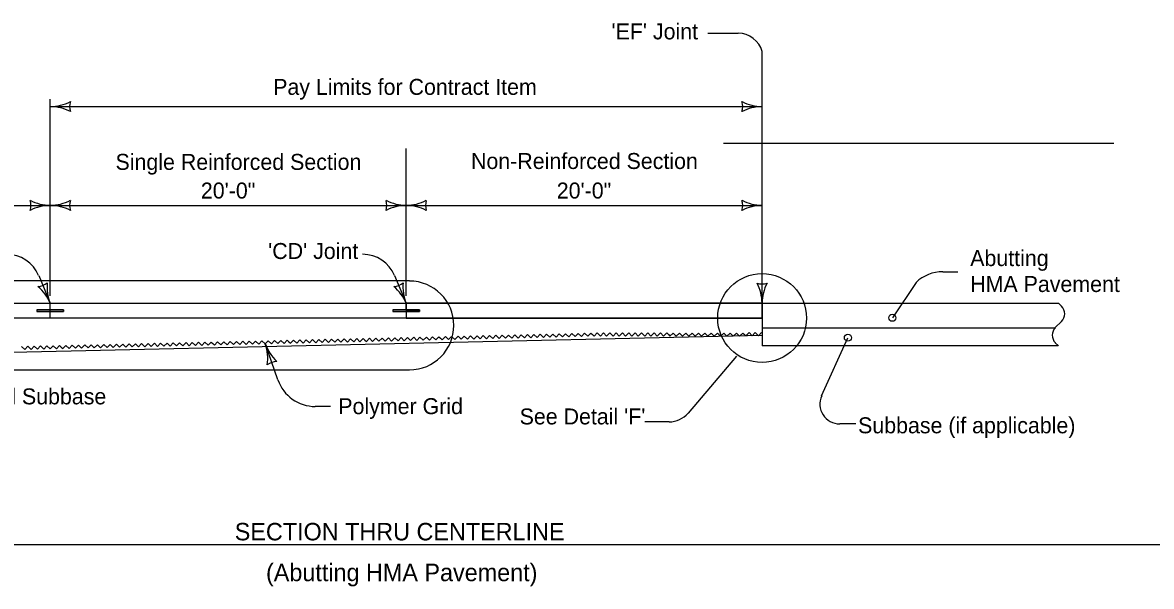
# Model space of a CAD drawing. Extents: x -2134860 to -2124557, y -2139046 to -2137324.
# Drawn here: x -2130560 to -2129429, y -2138083 to -2137518 of the extents above; entities that cross this region are included whole.
import ezdxf

# ---------------------------------------------------------------- set-up
doc = ezdxf.new("R2010")
doc.units = 0
for name, color, linetype in [('BridgeSuperStructureExisting', 7, 'Continuous'), ('dsnAlignmentCurveData', 7, 'Continuous'), ('dsnStdLabel', 7, 'Continuous'), ('TC_Barrier', 7, 'Continuous')]:
    doc.layers.add(name, color=color, linetype=linetype)

msp = doc.modelspace()

# ---------------------------------------------------------------- linework, layer by layer
at = {"layer": 'BridgeSuperStructureExisting'}
for p, q in [((-2129873.6, -2137528.5), (-2129843.1, -2137528.5)), ((-2129819.2, -2137799.1), (-2129819.2, -2137546.8)), ((-2130532, -2137791.7), (-2130532, -2137594.7)), ((-2130532, -2137602.1), (-2129819.2, -2137602.1)), ((-2129857.8, -2137638.6), (-2129466.9, -2137638.6)), ((-2130175.6, -2137791.7), (-2130175.6, -2137644.1)), ((-2130980.5, -2137701.1), (-2130532, -2137701.1)), ((-2130532, -2137701.1), (-2130175.6, -2137701.1)), ((-2130175.6, -2137701.1), (-2129819.2, -2137701.1)), ((-2130543.6, -2137771.4), (-2130532, -2137799.1)), ((-2130187.2, -2137771.3), (-2130175.6, -2137799.1)), ((-2129638.1, -2137767.6), (-2129623.3, -2137767.6)), ((-2130172.4, -2137776.8), (-2130977.5, -2137776.8)), ((-2129665.1, -2137778.2), (-2129688.8, -2137813.7)), ((-2130977.5, -2137799.1), (-2129819.2, -2137799.1)), ((-2130545.4, -2137805.6), (-2130518.7, -2137805.6)), ((-2130545.4, -2137807.5), (-2130518.7, -2137807.5)), ((-2130545.4, -2137807.5), (-2130518.7, -2137807.5)), ((-2130532, -2137814), (-2130532, -2137799.1)), ((-2130518.7, -2137805.6), (-2130518.7, -2137807.5)), ((-2130189, -2137805.6), (-2130162.3, -2137805.6)), ((-2130189, -2137807.5), (-2130162.3, -2137807.5)), ((-2129819.2, -2137799.1), (-2130175.6, -2137799.1)), ((-2130175.6, -2137799.1), (-2130175.6, -2137805.6)), ((-2130175.6, -2137799.1), (-2130175.6, -2137814)), ((-2130175.6, -2137805.6), (-2130162.3, -2137805.6)), ((-2130162.3, -2137807.5), (-2130175.6, -2137807.5)), ((-2130175.6, -2137807.5), (-2130175.6, -2137814)), ((-2130162.3, -2137805.6), (-2130162.3, -2137807.5)), ((-2130162.3, -2137805.6), (-2130162.3, -2137807.5)), ((-2129819.2, -2137814), (-2129819.2, -2137799.1)), ((-2129819.2, -2137799.1), (-2129522.4, -2137799.1)), ((-2129819.2, -2137799.1), (-2129819.2, -2137814)), ((-2129537, -2137799.1), (-2129537, -2137799.1)), ((-2129519.3, -2137802.2), (-2129522.4, -2137799.1)), ((-2129819.2, -2137814), (-2130977.5, -2137814)), ((-2130175.6, -2137814), (-2129819.2, -2137814)), ((-2129819.2, -2137814), (-2129819.2, -2137841.7)), ((-2129525.6, -2137823.6), (-2129519.3, -2137817.4)), ((-2129819.2, -2137831.6), (-2130943.9, -2137857)), ((-2129819.2, -2137823.9), (-2129525.8, -2137823.9)), ((-2130304.1, -2137876), (-2130316.6, -2137840.1)), ((-2129522.6, -2137841.7), (-2129819.2, -2137841.7)), ((-2129759.6, -2137892), (-2129733.3, -2137833.7)), ((-2129522.4, -2137841.9), (-2129525.6, -2137838.7)), ((-2129844.7, -2137852.1), (-2129893.3, -2137909.2)), ((-2130977.5, -2137865.9), (-2130172.4, -2137865.9)), ((-2130251.3, -2137902.6), (-2130266.7, -2137902.6)), ((-2129912.4, -2137918), (-2129936.6, -2137918)), ((-2129725.3, -2137920), (-2129741.5, -2137920))]:
    msp.add_line(p, q, dxfattribs=at)
for points in [[(-2130141.1, -2137834.2), (-2130139.5, -2137835.8), (-2130136.4, -2137832.5), (-2130133.2, -2137835.6), (-2130130.1, -2137832.4), (-2130126.8, -2137835.5), (-2130123.7, -2137832.2), (-2130120.5, -2137835.3), (-2130117.4, -2137832.1), (-2130114.2, -2137835.2), (-2130111.1, -2137831.9), (-2130107.8, -2137835), (-2130104.7, -2137831.8), (-2130101.5, -2137834.9), (-2130098.4, -2137831.6), (-2130095.2, -2137834.7), (-2130092.1, -2137831.5), (-2130088.8, -2137834.6), (-2130085.7, -2137831.3), (-2130082.5, -2137834.4), (-2130079.4, -2137831.2), (-2130076.2, -2137834.3), (-2130073.1, -2137831), (-2130069.8, -2137834.1), (-2130066.7, -2137830.9), (-2130065.1, -2137832.4)], [(-2130065.1, -2137832.4), (-2130063.5, -2137834), (-2130060.4, -2137830.7), (-2130057.2, -2137833.8), (-2130054.1, -2137830.6), (-2130050.8, -2137833.7), (-2130047.7, -2137830.4), (-2130044.5, -2137833.5), (-2130041.4, -2137830.3), (-2130038.2, -2137833.4), (-2130035.1, -2137830.1), (-2130031.8, -2137833.2), (-2130028.7, -2137830), (-2130025.5, -2137833.1), (-2130022.4, -2137829.8), (-2130019.2, -2137832.9), (-2130016.1, -2137829.7), (-2130012.8, -2137832.8), (-2130009.7, -2137829.5), (-2130006.5, -2137832.6), (-2130003.4, -2137829.4), (-2130000.2, -2137832.5), (-2129997.1, -2137829.3), (-2129993.8, -2137832.3), (-2129990.7, -2137829.1), (-2129989.1, -2137830.6)], [(-2129989.1, -2137830.5), (-2129987.5, -2137832.1), (-2129984.4, -2137828.9), (-2129981.2, -2137832.1), (-2129978, -2137828.9), (-2129974.9, -2137832.1), (-2129971.7, -2137828.9), (-2129968.5, -2137832.1), (-2129965.4, -2137828.9), (-2129962.2, -2137832.1), (-2129959, -2137828.9), (-2129955.9, -2137832), (-2129952.7, -2137828.9), (-2129949.5, -2137832), (-2129946.4, -2137828.9), (-2129943.2, -2137832), (-2129940, -2137828.9), (-2129936.8, -2137832), (-2129933.7, -2137828.9), (-2129930.5, -2137832), (-2129927.3, -2137828.8), (-2129924.2, -2137832), (-2129921, -2137828.8), (-2129917.8, -2137832), (-2129914.7, -2137828.8), (-2129913.1, -2137830.4)], [(-2129913.1, -2137830.6), (-2129911.5, -2137832.2), (-2129908.3, -2137829.1), (-2129905.2, -2137832.2), (-2129902, -2137829), (-2129898.8, -2137832.2), (-2129895.7, -2137829), (-2129892.5, -2137832.2), (-2129889.3, -2137829), (-2129886.2, -2137832.2), (-2129883, -2137829), (-2129879.8, -2137832.2), (-2129876.7, -2137829), (-2129873.5, -2137832.2), (-2129870.3, -2137829), (-2129867.1, -2137832.2), (-2129864, -2137829), (-2129860.8, -2137832.2), (-2129857.6, -2137829), (-2129854.5, -2137832.2), (-2129851.3, -2137829), (-2129848.1, -2137832.1), (-2129845, -2137829), (-2129841.8, -2137832.1), (-2129838.6, -2137829), (-2129837.1, -2137830.5)], [(-2129837.1, -2137830.2), (-2129835.5, -2137831.8), (-2129832.3, -2137828.6), (-2129829.2, -2137831.8), (-2129826, -2137828.6), (-2129822.8, -2137831.8), (-2129819.7, -2137828.6), (-2129819.2, -2137829.1)], [(-2130560.8, -2137842.5), (-2130557.6, -2137845.6), (-2130554.5, -2137842.3), (-2130551.2, -2137845.4), (-2130548.1, -2137842.2), (-2130544.9, -2137845.3), (-2130541.8, -2137842), (-2130538.6, -2137845.1), (-2130535.5, -2137841.9), (-2130532.2, -2137845), (-2130529.1, -2137841.7), (-2130525.9, -2137844.8), (-2130522.8, -2137841.6), (-2130521.2, -2137843.1)], [(-2130521.2, -2137843.1), (-2130519.6, -2137844.6), (-2130516.5, -2137841.4), (-2130513.2, -2137844.5), (-2130510.1, -2137841.2), (-2130506.9, -2137844.3), (-2130503.8, -2137841.1), (-2130500.6, -2137844.2), (-2130497.5, -2137841), (-2130494.2, -2137844), (-2130491.1, -2137840.8), (-2130487.9, -2137843.9), (-2130484.8, -2137840.7), (-2130481.6, -2137843.8), (-2130478.5, -2137840.5), (-2130475.2, -2137843.6), (-2130472.1, -2137840.4), (-2130468.9, -2137843.5), (-2130465.8, -2137840.2), (-2130462.6, -2137843.3), (-2130459.5, -2137840.1), (-2130456.2, -2137843.2), (-2130453.1, -2137839.9), (-2130449.9, -2137843), (-2130446.8, -2137839.8), (-2130445.2, -2137841.3)], [(-2130445.2, -2137841.3), (-2130443.6, -2137842.8), (-2130440.5, -2137839.6), (-2130437.2, -2137842.7), (-2130434.1, -2137839.5), (-2130430.9, -2137842.5), (-2130427.8, -2137839.3), (-2130424.6, -2137842.4), (-2130421.5, -2137839.2), (-2130418.2, -2137842.3), (-2130415.1, -2137839), (-2130411.9, -2137842.1), (-2130408.8, -2137838.9), (-2130405.5, -2137842), (-2130402.5, -2137838.7), (-2130399.2, -2137841.8), (-2130396.1, -2137838.6), (-2130392.9, -2137841.7), (-2130389.8, -2137838.4), (-2130386.5, -2137841.5), (-2130383.5, -2137838.3), (-2130380.2, -2137841.4), (-2130377.1, -2137838.1), (-2130373.9, -2137841.2), (-2130370.8, -2137838), (-2130369.2, -2137839.5)], [(-2130369.2, -2137839.5), (-2130367.5, -2137841.1), (-2130364.4, -2137837.9), (-2130361.2, -2137840.9), (-2130358.1, -2137837.7), (-2130354.9, -2137840.8), (-2130351.8, -2137837.6), (-2130348.5, -2137840.6), (-2130345.4, -2137837.4), (-2130342.2, -2137840.5), (-2130339.1, -2137837.3), (-2130335.9, -2137840.4), (-2130332.8, -2137837.1), (-2130329.5, -2137840.2), (-2130326.4, -2137837), (-2130323.2, -2137840.1), (-2130320.1, -2137836.8), (-2130316.9, -2137839.9), (-2130313.8, -2137836.7), (-2130310.5, -2137839.8), (-2130307.4, -2137836.5), (-2130304.2, -2137839.6), (-2130301.1, -2137836.4), (-2130297.9, -2137839.5), (-2130294.8, -2137836.2), (-2130293.2, -2137837.8)], [(-2130293.2, -2137837.8), (-2130291.5, -2137839.3), (-2130288.4, -2137836.1), (-2130285.2, -2137839.2), (-2130282.1, -2137835.9), (-2130278.9, -2137839), (-2130275.8, -2137835.8), (-2130272.5, -2137838.9), (-2130269.4, -2137835.6), (-2130266.2, -2137838.7), (-2130263.1, -2137835.5), (-2130259.9, -2137838.6), (-2130256.8, -2137835.3), (-2130253.5, -2137838.4), (-2130250.4, -2137835.2), (-2130247.2, -2137838.3), (-2130244.1, -2137835), (-2130240.9, -2137838.1), (-2130237.8, -2137834.9), (-2130234.5, -2137838), (-2130231.4, -2137834.7), (-2130228.2, -2137837.8), (-2130225.1, -2137834.6), (-2130221.9, -2137837.7), (-2130218.8, -2137834.4), (-2130217.1, -2137836)], [(-2130217.1, -2137836), (-2130215.5, -2137837.6), (-2130212.4, -2137834.3), (-2130209.2, -2137837.4), (-2130206.1, -2137834.2), (-2130202.9, -2137837.3), (-2130199.8, -2137834), (-2130196.5, -2137837.1), (-2130193.4, -2137833.9), (-2130190.2, -2137837), (-2130187.1, -2137833.7), (-2130183.8, -2137836.8), (-2130180.8, -2137833.6), (-2130177.5, -2137836.7), (-2130174.4, -2137833.4), (-2130171.2, -2137836.5), (-2130168.1, -2137833.3), (-2130164.8, -2137836.4), (-2130161.8, -2137833.1), (-2130158.5, -2137836.2), (-2130155.4, -2137833), (-2130152.2, -2137836.1), (-2130149.1, -2137832.8), (-2130145.8, -2137835.9), (-2130142.8, -2137832.7), (-2130141.1, -2137834.2)]]:
    msp.add_lwpolyline(points, dxfattribs=at)
msp.add_circle((-2129819.2, -2137814), 44.5, dxfattribs=at)
for centre, radius, start, end in [((-2129843.1, -2137553.3), 24.7, 15.0299, 90), ((-2130532, -2137559.3), 42.7, 270, 298.0725), ((-2130532, -2137644.8), 42.7, 61.9275, 90), ((-2130496.2, -2137602.1), 16.5, 162.2666, 197.7334), ((-2129855.1, -2137602.1), 16.5, 342.2666, 17.7333), ((-2129819.2, -2137559.3), 42.7, 241.9275, 270), ((-2129819.2, -2137644.8), 42.7, 90, 118.0725), ((-2130567.9, -2137701.1), 16.5, 342.2666, 17.7333), ((-2130532, -2137658.3), 42.7, 241.9275, 270), ((-2130532, -2137743.8), 42.7, 90, 118.0725), ((-2130532, -2137658.3), 42.7, 270, 298.0725), ((-2130532, -2137743.8), 42.7, 61.9275, 90), ((-2130496.2, -2137701.1), 16.5, 162.2666, 197.7334), ((-2130211.5, -2137701.1), 16.5, 342.2666, 17.7333), ((-2130175.6, -2137658.3), 42.7, 241.9275, 270), ((-2130175.6, -2137743.8), 42.7, 90, 118.0725), ((-2130175.6, -2137658.3), 42.7, 270, 298.0725), ((-2130175.6, -2137743.8), 42.7, 61.9275, 90), ((-2130139.8, -2137701.1), 16.5, 162.2666, 197.7334), ((-2129855.1, -2137701.1), 16.5, 342.2666, 17.7333), ((-2129819.2, -2137658.3), 42.7, 241.9275, 270), ((-2129819.2, -2137743.8), 42.7, 90, 118.0725), ((-2130575.6, -2137784.7), 34.6, 22.5907, 90), ((-2130219.2, -2137784.7), 34.6, 22.5907, 90), ((-2129638.1, -2137807.2), 39.6, 90, 132.998), ((-2130545.8, -2137766), 16.5, 274.8595, 310.3262), ((-2130571.5, -2137815.5), 42.7, 22.5928, 50.6653), ((-2130492.6, -2137782.7), 42.7, 174.5203, 202.5928), ((-2130189.4, -2137766), 16.5, 274.8572, 310.3239), ((-2130215.1, -2137815.5), 42.7, 22.5905, 50.663), ((-2130136.2, -2137782.7), 42.7, 174.5181, 202.5905), ((-2130172.4, -2137821.4), 44.5, 270.0002, 90), ((-2129819.2, -2137763.3), 16.5, 252.2666, 287.7333), ((-2129862, -2137799.1), 42.7, 360, 28.0725), ((-2129776.5, -2137799.1), 42.7, 151.9275, 180), ((-2129526.9, -2137809.8), 10.7, 315, 45), ((-2129518, -2137831.2), 10.7, 135, 225), ((-2130276.2, -2137826.1), 42.7, 199.1779, 227.2504), ((-2130357, -2137854.2), 42.7, 351.1054, 19.1779), ((-2130304.8, -2137874), 16.5, 91.4446, 126.9113), ((-2130266.7, -2137863), 39.6, 199.1769, 270), ((-2129741.5, -2137900.2), 19.8, 155.762, 270), ((-2129912.4, -2137893), 25, 270, 319.6052)]:
    msp.add_arc(centre, radius, start, end, dxfattribs=at)
at = {"layer": 'dsnAlignmentCurveData'}
msp.add_line((-2131334.4, -2138040.9), (-2128199.4, -2138040.9), dxfattribs=at)
at = {"layer": 'dsnStdLabel'}
for p, q in [((-2130545.4, -2137805.6), (-2130545.4, -2137807.5)), ((-2130545.4, -2137805.6), (-2130545.4, -2137807.5)), ((-2130518.7, -2137805.6), (-2130545.4, -2137805.6)), ((-2130545.4, -2137805.6), (-2130532, -2137805.6)), ((-2130532, -2137814), (-2130532.1, -2137807.5)), ((-2130532, -2137805.6), (-2130532, -2137799.1)), ((-2130532, -2137805.6), (-2130532, -2137799.1)), ((-2130532, -2137799.1), (-2130175.6, -2137799.1)), ((-2130518.7, -2137805.6), (-2130532, -2137805.6)), ((-2130518.7, -2137805.6), (-2130532, -2137805.6)), ((-2130532, -2137814), (-2130532, -2137807.5)), ((-2130532, -2137807.5), (-2130518.7, -2137807.5)), ((-2130518.7, -2137807.5), (-2130518.7, -2137805.6)), ((-2130518.7, -2137807.5), (-2130518.7, -2137805.6)), ((-2130189, -2137805.6), (-2130189, -2137807.5)), ((-2130175.6, -2137805.6), (-2130189, -2137805.6)), ((-2130189, -2137805.6), (-2130189, -2137807.5)), ((-2130189, -2137807.5), (-2130175.6, -2137807.5)), ((-2130175.6, -2137805.6), (-2130175.6, -2137799.1)), ((-2130175.6, -2137799.1), (-2130175.6, -2137805.6)), ((-2130162.3, -2137805.6), (-2130175.6, -2137805.6)), ((-2130175.6, -2137807.5), (-2130175.6, -2137814)), ((-2130175.6, -2137814), (-2130532, -2137814))]:
    msp.add_line(p, q, dxfattribs=at)
at = {"layer": 'TC_Barrier'}
for centre in [(-2129688.8, -2137813.7), (-2129733.3, -2137833.7)]:
    msp.add_circle(centre, 3.54, dxfattribs=at)

# ---------------------------------------------------------------- texts
at = {"layer": 'BridgeSuperStructureExisting'}
msp.add_text('SECTION THRU CENTERLINE', height=17.5, dxfattribs=at).set_placement((-2130347.3, -2138036.8))
at = {"layer": 'dsnStdLabel'}
for s, height, p in [("'EF' Joint", 16, (-2129970, -2137534.7)), ('Pay Limits for Contract Item', 16, (-2130308.8, -2137590.3)), ('Single Reinforced Section', 16, (-2130466.7, -2137665.5)), ('Non-Reinforced Section', 16, (-2130110.7, -2137664.6)), ('20\'-0"', 16, (-2130381.2, -2137694.2)), ('20\'-0"', 16, (-2130024.8, -2137694.2)), ("'CD' Joint", 16, (-2130313.8, -2137754.8)), ('Abutting', 16, (-2129610.8, -2137761.9)), ('HMA Pavement', 16, (-2129610.8, -2137787.9)), ('Modified Subbase', 16, (-2130647.2, -2137900.5)), ('Polymer Grid', 16, (-2130243.6, -2137910.3)), ("See Detail 'F'", 16, (-2130062, -2137920.6)), ('Subbase (if applicable)', 16, (-2129723.1, -2137929.5)), ('(Abutting HMA Pavement)', 17.5, (-2130316, -2138077.7))]:
    msp.add_text(s, height=height, dxfattribs=at).set_placement(p)

doc.saveas('drawing.dxf')
